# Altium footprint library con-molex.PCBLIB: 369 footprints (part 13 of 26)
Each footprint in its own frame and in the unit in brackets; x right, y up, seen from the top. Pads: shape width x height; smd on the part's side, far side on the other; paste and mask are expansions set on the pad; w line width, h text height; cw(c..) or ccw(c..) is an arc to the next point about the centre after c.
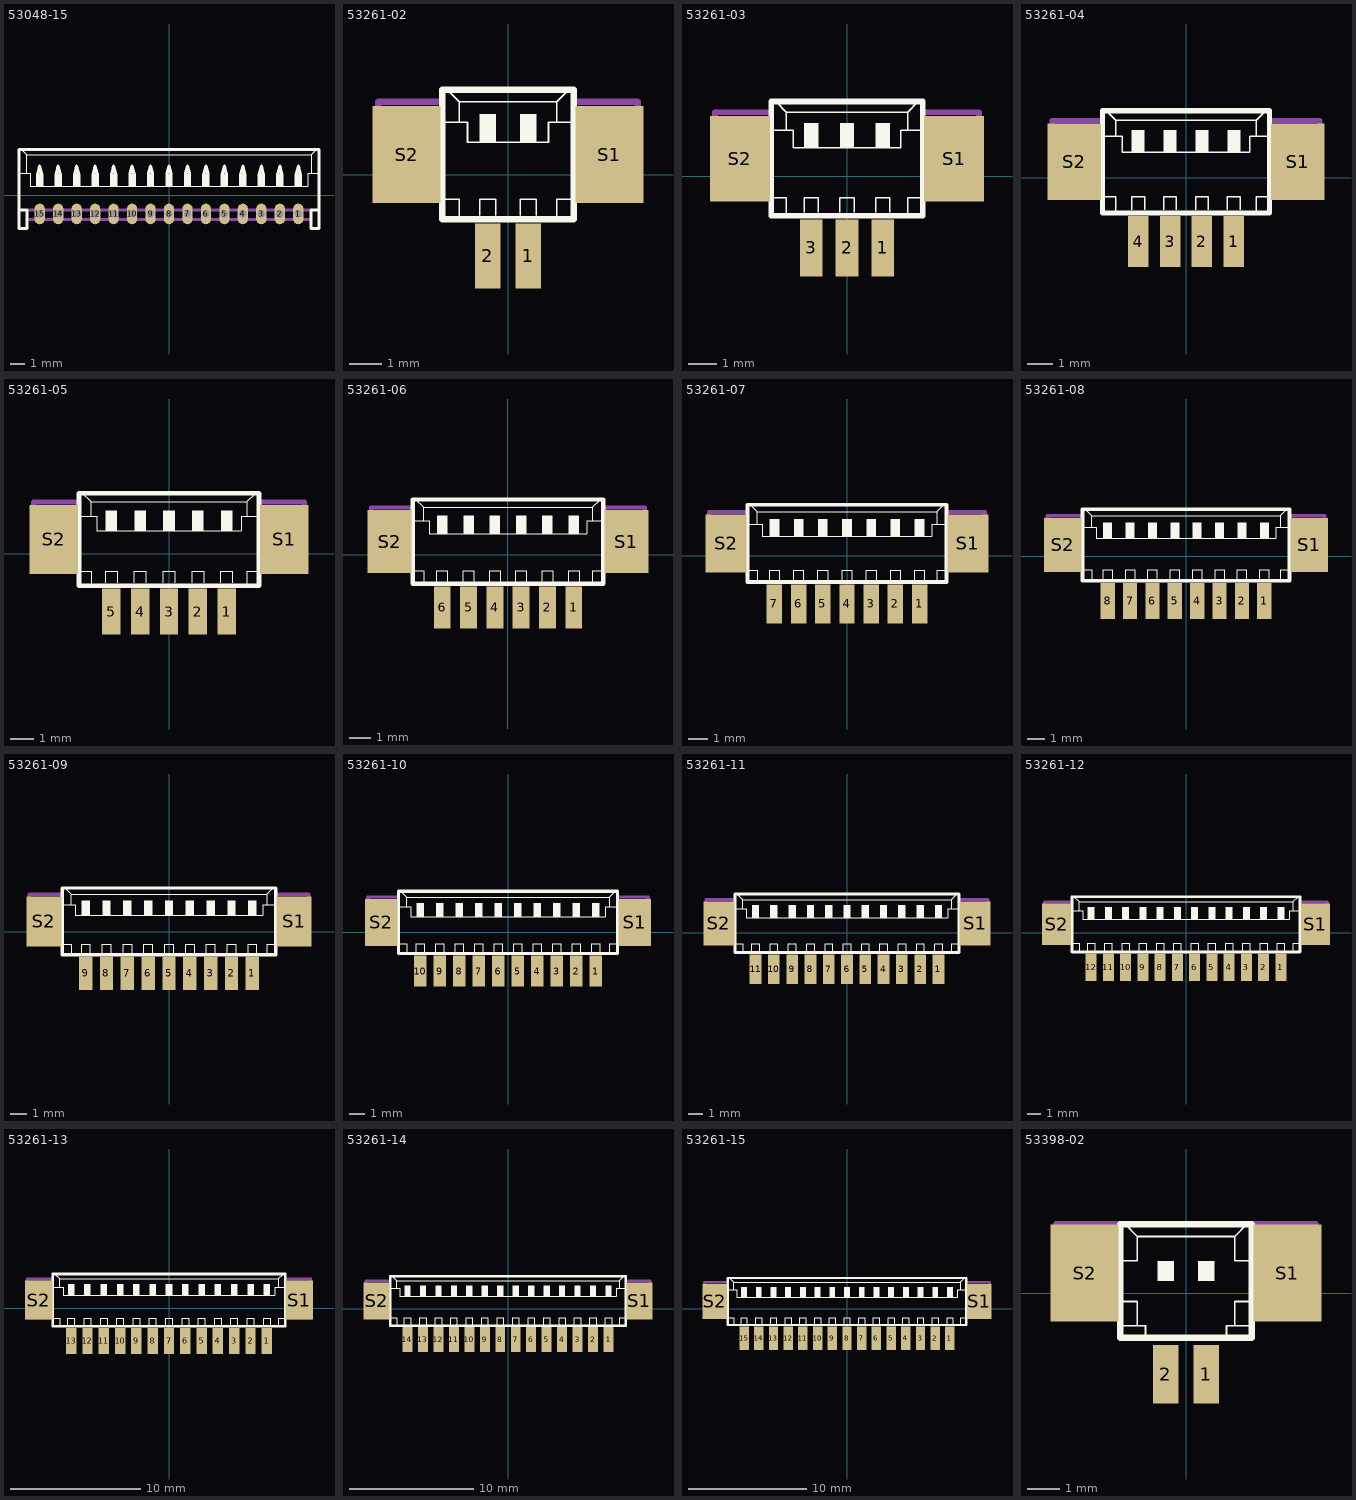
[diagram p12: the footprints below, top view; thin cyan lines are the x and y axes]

## 53048-15 [mil]
pads (15):
  oval 27.5x55 hole 19.69: 1(344.49,-49.21) 2(295.28,-49.21) 3(246.06,-49.21) 4(196.85,-49.21) 5(147.64,-49.21) 6(98.43,-49.21) 7(49.21,-49.21) 8(0,-49.21) 9(-49.21,-49.21) 10(-98.43,-49.21) 11(-147.64,-49.21) 12(-196.85,-49.21) 13(-246.06,-49.21) 14(-295.28,-49.21) 15(-344.49,-49.21)
Top Overlay:
  rectangle: -354.33,24.61 -334.65,59.06
  rectangle: -305.12,24.61 -285.43,59.06
  rectangle: -255.91,24.61 -236.22,59.06
  rectangle: -206.69,24.61 -187.01,59.06
  rectangle: -157.48,24.61 -137.8,59.06
  rectangle: -108.27,24.61 -88.58,59.06
  rectangle: -59.06,24.61 -39.37,59.06
  rectangle: -9.84,24.61 9.84,59.06
  rectangle: 39.37,24.61 59.06,59.06
  rectangle: 88.58,24.61 108.27,59.06
  rectangle: 137.8,24.61 157.48,59.06
  rectangle: 187.01,24.61 206.69,59.06
  rectangle: 236.22,24.61 255.91,59.06
  rectangle: 285.43,24.61 305.12,59.06
  rectangle: 334.65,24.61 354.33,59.06
  lines w2: -398.62,59.06 -378.94,59.06 ; -393.7,123.03 -378.94,108.27 ; 393.7,123.03 378.94,108.27 ; 398.62,59.06 378.94,59.06 ; -378.94,59.06 -369.09,59.06 -369.09,24.61 369.09,24.61 369.09,59.06 378.94,59.06 ; -378.94,59.06 -378.94,108.27 ; -378.94,108.27 378.94,108.27 ; 378.94,59.06 378.94,108.27
  lines w8: -398.62,-39.37 -378.94,-39.37 -378.94,-88.58 -399.61,-88.58 -399.61,123.03 -393.7,123.03 393.7,123.03 399.61,123.03 399.61,-88.58 378.94,-88.58 378.94,-39.37 398.62,-39.37 ; -349.41,59.06 -344.49,78.74 -339.57,59.06 ; -300.2,59.06 -295.28,78.74 -290.35,59.06 ; -250.98,59.06 -246.06,78.74 -241.14,59.06 ; -201.77,59.06 -196.85,78.74 -191.93,59.06 ; -152.56,59.06 -147.64,78.74 -142.72,59.06 ; -103.35,59.06 -98.43,78.74 -93.5,59.06 ; -54.13,59.06 -49.21,78.74 -44.29,59.06 ; -4.92,59.06 0,78.74 4.92,59.06 ; 44.29,59.06 49.21,78.74 54.13,59.06 ; 93.5,59.06 98.43,78.74 103.35,59.06 ; 142.72,59.06 147.64,78.74 152.56,59.06 ; 191.93,59.06 196.85,78.74 201.77,59.06 ; 241.14,59.06 246.06,78.74 250.98,59.06 ; 290.35,59.06 295.28,78.74 300.2,59.06 ; 339.57,59.06 344.49,78.74 349.41,59.06
Mechanical 16:
  rectangle: -354.33,-59.06 -334.65,-39.37
  rectangle: -305.12,-59.06 -285.43,-39.37
  rectangle: -255.91,-59.06 -236.22,-39.37
  rectangle: -206.69,-59.06 -187.01,-39.37
  rectangle: -157.48,-59.06 -137.8,-39.37
  rectangle: -108.27,-59.06 -88.58,-39.37
  rectangle: -59.06,-59.06 -39.37,-39.37
  rectangle: -9.84,-59.06 9.84,-39.37
  rectangle: 39.37,-59.06 59.06,-39.37
  rectangle: 88.58,-59.06 108.27,-39.37
  rectangle: 137.8,-59.06 157.48,-39.37
  rectangle: 187.01,-59.06 206.69,-39.37
  rectangle: 236.22,-59.06 255.91,-39.37
  rectangle: 285.43,-59.06 305.12,-39.37
  rectangle: 334.65,-59.06 354.33,-39.37
  lines w8: -378.94,-63.98 -359.25,-63.98 -354.33,-59.06 ; -378.94,-39.37 378.94,-39.37 ; -334.65,-59.06 -329.72,-63.98 -310.04,-63.98 -305.12,-59.06 ; -285.43,-59.06 -280.51,-63.98 -260.83,-63.98 -255.91,-59.06 ; -236.22,-59.06 -231.3,-63.98 -211.61,-63.98 -206.69,-59.06 ; -187.01,-59.06 -182.09,-63.98 -162.4,-63.98 -157.48,-59.06 ; -137.8,-59.06 -132.87,-63.98 -113.19,-63.98 -108.27,-59.06 ; -88.58,-59.06 -83.66,-63.98 -63.98,-63.98 -59.06,-59.06 ; -39.37,-59.06 -34.45,-63.98 -14.76,-63.98 -9.84,-59.06 ; 9.84,-59.06 14.76,-63.98 34.45,-63.98 39.37,-59.06 ; 59.06,-59.06 63.98,-63.98 83.66,-63.98 88.58,-59.06 ; 108.27,-59.06 113.19,-63.98 132.87,-63.98 137.8,-59.06 ; 157.48,-59.06 162.4,-63.98 182.09,-63.98 187.01,-59.06 ; 206.69,-59.06 211.61,-63.98 231.3,-63.98 236.22,-59.06 ; 255.91,-59.06 260.83,-63.98 280.51,-63.98 285.43,-59.06 ; 305.12,-59.06 310.04,-63.98 329.72,-63.98 334.65,-59.06 ; 354.33,-59.06 359.25,-63.98 378.94,-63.98

## 53261-02 [mm]
pads (4):
  rect 0.8x2 smd: 1(0.625,-2.5) 2(-0.625,-2.5)
  rect 2.1x3 smd: S1(3.125,0.625) S2(-3.125,0.625)
Top Overlay:
  rectangle: -0.875,1 -0.375,1.875
  rectangle: 0.375,1 0.875,1.875
  lines w0.051: -2,-0.75 -1.5,-0.75 -1.5,-1.375 ; -2,1.625 -1.5,1.625 ; -1.875,2.625 -1.5,2.25 ; -0.875,-1.25 -0.875,-0.75 -0.375,-0.75 -0.375,-1.25 ; 0.375,-1.25 0.375,-0.75 0.875,-0.75 0.875,-1.25 ; 1.5,-1.375 1.5,-0.75 2,-0.75 ; 1.875,2.625 1.5,2.25 ; 2,1.625 1.5,1.625 ; -1.5,1.625 -1.25,1.625 -1.25,1 1.25,1 1.25,1.625 1.5,1.625 ; -1.5,1.625 -1.5,2.25 ; -1.5,2.25 1.5,2.25 ; 1.5,1.625 1.5,2.25
  lines w0.203: -2.025,-1.375 -1.5,-1.375 1.5,-1.375 2.025,-1.375 2.025,2.625 1.875,2.625 -1.875,2.625 -2.025,2.625 -2.025,-1.375
Mechanical 16:
  lines w0.203: -2.125,-0.75 -4,-0.75 -4,2.25 -2.125,2.25 ; 2.125,-0.75 4,-0.75 4,2.25 2.125,2.25
  text "1" at 2.5,-0.25 h2.99

## 53261-03 [mm]
pads (5):
  rect 0.8x2 smd: 1(1.25,-2.5) 2(0,-2.5) 3(-1.25,-2.5)
  rect 2.1x3 smd: S1(3.75,0.625) S2(-3.75,0.625)
Top Overlay:
  rectangle: -1.5,1 -1,1.875
  rectangle: -0.25,1 0.25,1.875
  rectangle: 1,1 1.5,1.875
  lines w0.051: -2.625,-0.75 -2.125,-0.75 -2.125,-1.375 ; -2.625,1.625 -2.125,1.625 ; -2.5,2.625 -2.125,2.25 ; -1.5,-1.25 -1.5,-0.75 -1,-0.75 -1,-1.25 ; -0.25,-1.25 -0.25,-0.75 0.25,-0.75 0.25,-1.25 ; 1,-1.25 1,-0.75 1.5,-0.75 1.5,-1.25 ; 2.125,-1.375 2.125,-0.75 2.625,-0.75 ; 2.5,2.625 2.125,2.25 ; 2.625,1.625 2.125,1.625 ; -2.125,1.625 -1.875,1.625 -1.875,1 1.875,1 1.875,1.625 2.125,1.625 ; -2.125,1.625 -2.125,2.25 ; -2.125,2.25 2.125,2.25 ; 2.125,1.625 2.125,2.25
  lines w0.203: -2.65,-1.375 -2.125,-1.375 2.125,-1.375 2.65,-1.375 2.65,2.625 2.5,2.625 -2.5,2.625 -2.65,2.625 -2.65,-1.375
Mechanical 16:
  lines w0.203: -2.75,-0.75 -4.625,-0.75 -4.625,2.25 -2.75,2.25 ; 2.75,-0.75 4.625,-0.75 4.625,2.25 2.75,2.25
  text "1" at 3.125,-0.25 h2.99

## 53261-04 [mm]
pads (6):
  rect 0.8x2 smd: 1(1.875,-2.5) 2(0.625,-2.5) 3(-0.625,-2.5) 4(-1.875,-2.5)
  rect 2.1x3 smd: S1(4.375,0.625) S2(-4.375,0.625)
Top Overlay:
  rectangle: -2.125,1 -1.625,1.875
  rectangle: -0.875,1 -0.375,1.875
  rectangle: 0.375,1 0.875,1.875
  rectangle: 1.625,1 2.125,1.875
  lines w0.051: -3.25,-0.75 -2.75,-0.75 -2.75,-1.375 ; -3.25,1.625 -2.75,1.625 ; -3.125,2.625 -2.75,2.25 ; -2.125,-1.25 -2.125,-0.75 -1.625,-0.75 -1.625,-1.25 ; -0.875,-1.25 -0.875,-0.75 -0.375,-0.75 -0.375,-1.25 ; 0.375,-1.25 0.375,-0.75 0.875,-0.75 0.875,-1.25 ; 1.625,-1.25 1.625,-0.75 2.125,-0.75 2.125,-1.25 ; 2.75,-1.375 2.75,-0.75 3.25,-0.75 ; 3.125,2.625 2.75,2.25 ; 3.25,1.625 2.75,1.625 ; -2.75,1.625 -2.5,1.625 -2.5,1 2.5,1 2.5,1.625 2.75,1.625 ; -2.75,1.625 -2.75,2.25 ; -2.75,2.25 2.75,2.25 ; 2.75,1.625 2.75,2.25
  lines w0.203: -3.275,-1.375 -2.75,-1.375 2.75,-1.375 3.275,-1.375 3.275,2.625 3.125,2.625 -3.125,2.625 -3.275,2.625 -3.275,-1.375
Mechanical 16:
  lines w0.203: -3.375,-0.75 -5.25,-0.75 -5.25,2.25 -3.375,2.25 ; 3.375,-0.75 5.25,-0.75 5.25,2.25 3.375,2.25
  text "1" at 3.75,-0.25 h2.99

## 53261-05 [mm]
pads (7):
  rect 0.8x2 smd: 1(2.5,-2.5) 2(1.25,-2.5) 3(0,-2.5) 4(-1.25,-2.5) 5(-2.5,-2.5)
  rect 2.1x3 smd: S1(5,0.625) S2(-5,0.625)
Top Overlay:
  rectangle: -2.75,1 -2.25,1.875
  rectangle: -1.5,1 -1,1.875
  rectangle: -0.25,1 0.25,1.875
  rectangle: 1,1 1.5,1.875
  rectangle: 2.25,1 2.75,1.875
  lines w0.051: -3.875,-0.75 -3.375,-0.75 -3.375,-1.375 ; -3.875,1.625 -3.375,1.625 ; -3.75,2.625 -3.375,2.25 ; -2.75,-1.25 -2.75,-0.75 -2.25,-0.75 -2.25,-1.25 ; -1.5,-1.25 -1.5,-0.75 -1,-0.75 -1,-1.25 ; -0.25,-1.25 -0.25,-0.75 0.25,-0.75 0.25,-1.25 ; 1,-1.25 1,-0.75 1.5,-0.75 1.5,-1.25 ; 2.25,-1.25 2.25,-0.75 2.75,-0.75 2.75,-1.25 ; 3.375,-1.375 3.375,-0.75 3.875,-0.75 ; 3.75,2.625 3.375,2.25 ; 3.875,1.625 3.375,1.625 ; -3.375,1.625 -3.125,1.625 -3.125,1 3.125,1 3.125,1.625 3.375,1.625 ; -3.375,1.625 -3.375,2.25 ; -3.375,2.25 3.375,2.25 ; 3.375,1.625 3.375,2.25
  lines w0.203: -3.9,-1.375 -3.375,-1.375 3.375,-1.375 3.9,-1.375 3.9,2.625 3.75,2.625 -3.75,2.625 -3.9,2.625 -3.9,-1.375
Mechanical 16:
  lines w0.203: -4,-0.75 -5.875,-0.75 -5.875,2.25 -4,2.25 ; 4,-0.75 5.875,-0.75 5.875,2.25 4,2.25
  text "1" at 4.375,-0.25 h2.99

## 53261-06 [mm]
pads (8):
  rect 0.8x2 smd: 1(3.125,-2.5) 2(1.875,-2.5) 3(0.625,-2.5) 4(-0.625,-2.5) 5(-1.875,-2.5) 6(-3.125,-2.5)
  rect 2.1x3 smd: S1(5.625,0.625) S2(-5.625,0.625)
Top Overlay:
  rectangle: -3.375,1 -2.875,1.875
  rectangle: -2.125,1 -1.625,1.875
  rectangle: -0.875,1 -0.375,1.875
  rectangle: 0.375,1 0.875,1.875
  rectangle: 1.625,1 2.125,1.875
  rectangle: 2.875,1 3.375,1.875
  lines w0.051: -4.5,-0.75 -4,-0.75 -4,-1.375 ; -4.5,1.625 -4,1.625 ; -4.375,2.625 -4,2.25 ; -3.375,-1.25 -3.375,-0.75 -2.875,-0.75 -2.875,-1.25 ; -2.125,-1.25 -2.125,-0.75 -1.625,-0.75 -1.625,-1.25 ; -0.875,-1.25 -0.875,-0.75 -0.375,-0.75 -0.375,-1.25 ; 0.375,-1.25 0.375,-0.75 0.875,-0.75 0.875,-1.25 ; 1.625,-1.25 1.625,-0.75 2.125,-0.75 2.125,-1.25 ; 2.875,-1.25 2.875,-0.75 3.375,-0.75 3.375,-1.25 ; 4,-1.375 4,-0.75 4.5,-0.75 ; 4.375,2.625 4,2.25 ; 4.5,1.625 4,1.625 ; -4,1.625 -3.75,1.625 -3.75,1 3.75,1 3.75,1.625 4,1.625 ; -4,1.625 -4,2.25 ; -4,2.25 4,2.25 ; 4,1.625 4,2.25
  lines w0.203: -4.525,-1.375 -4,-1.375 4,-1.375 4.525,-1.375 4.525,2.625 4.375,2.625 -4.375,2.625 -4.525,2.625 -4.525,-1.375
Mechanical 16:
  lines w0.203: -4.625,-0.75 -6.5,-0.75 -6.5,2.25 -4.625,2.25 ; 4.625,-0.75 6.5,-0.75 6.5,2.25 4.625,2.25
  text "1" at 5,-0.25 h2.99

## 53261-07 [mm]
pads (9):
  rect 0.8x2 smd: 1(3.75,-2.5) 2(2.5,-2.5) 3(1.25,-2.5) 4(0,-2.5) 5(-1.25,-2.5) 6(-2.5,-2.5) 7(-3.75,-2.5)
  rect 2.1x3 smd: S1(6.25,0.625) S2(-6.25,0.625)
Top Overlay:
  rectangle: -4,1 -3.5,1.875
  rectangle: -2.75,1 -2.25,1.875
  rectangle: -1.5,1 -1,1.875
  rectangle: -0.25,1 0.25,1.875
  rectangle: 1,1 1.5,1.875
  rectangle: 2.25,1 2.75,1.875
  rectangle: 3.5,1 4,1.875
  lines w0.051: -5.125,-0.75 -4.625,-0.75 -4.625,-1.375 ; -5.125,1.625 -4.625,1.625 ; -5,2.625 -4.625,2.25 ; -4,-1.25 -4,-0.75 -3.5,-0.75 -3.5,-1.25 ; -2.75,-1.25 -2.75,-0.75 -2.25,-0.75 -2.25,-1.25 ; -1.5,-1.25 -1.5,-0.75 -1,-0.75 -1,-1.25 ; -0.25,-1.25 -0.25,-0.75 0.25,-0.75 0.25,-1.25 ; 1,-1.25 1,-0.75 1.5,-0.75 1.5,-1.25 ; 2.25,-1.25 2.25,-0.75 2.75,-0.75 2.75,-1.25 ; 3.5,-1.25 3.5,-0.75 4,-0.75 4,-1.25 ; 4.625,-1.375 4.625,-0.75 5.125,-0.75 ; 5,2.625 4.625,2.25 ; 5.125,1.625 4.625,1.625 ; -4.625,1.625 -4.375,1.625 -4.375,1 4.375,1 4.375,1.625 4.625,1.625 ; -4.625,1.625 -4.625,2.25 ; -4.625,2.25 4.625,2.25 ; 4.625,1.625 4.625,2.25
  lines w0.203: -5.15,-1.375 -4.625,-1.375 4.625,-1.375 5.15,-1.375 5.15,2.625 5,2.625 -5,2.625 -5.15,2.625 -5.15,-1.375
Mechanical 16:
  lines w0.203: -5.25,-0.75 -7.125,-0.75 -7.125,2.25 -5.25,2.25 ; 5.25,-0.75 7.125,-0.75 7.125,2.25 5.25,2.25
  text "1" at 5.75,-0.25 h2.99

## 53261-08 [mm]
pads (10):
  rect 0.8x2 smd: 1(4.375,-2.5) 2(3.125,-2.5) 3(1.875,-2.5) 4(0.625,-2.5) 5(-0.625,-2.5) 6(-1.875,-2.5) 7(-3.125,-2.5) 8(-4.375,-2.5)
  rect 2.1x3 smd: S1(6.875,0.625) S2(-6.875,0.625)
Top Overlay:
  rectangle: -4.625,1 -4.125,1.875
  rectangle: -3.375,1 -2.875,1.875
  rectangle: -2.125,1 -1.625,1.875
  rectangle: -0.875,1 -0.375,1.875
  rectangle: 0.375,1 0.875,1.875
  rectangle: 1.625,1 2.125,1.875
  rectangle: 2.875,1 3.375,1.875
  rectangle: 4.125,1 4.625,1.875
  lines w0.051: -5.75,-0.75 -5.25,-0.75 -5.25,-1.375 ; -5.75,1.625 -5.25,1.625 ; -5.625,2.625 -5.25,2.25 ; -4.625,-1.25 -4.625,-0.75 -4.125,-0.75 -4.125,-1.25 ; -3.375,-1.25 -3.375,-0.75 -2.875,-0.75 -2.875,-1.25 ; -2.125,-1.25 -2.125,-0.75 -1.625,-0.75 -1.625,-1.25 ; -0.875,-1.25 -0.875,-0.75 -0.375,-0.75 -0.375,-1.25 ; 0.375,-1.25 0.375,-0.75 0.875,-0.75 0.875,-1.25 ; 1.625,-1.25 1.625,-0.75 2.125,-0.75 2.125,-1.25 ; 2.875,-1.25 2.875,-0.75 3.375,-0.75 3.375,-1.25 ; 4.125,-1.25 4.125,-0.75 4.625,-0.75 4.625,-1.25 ; 5.25,-1.375 5.25,-0.75 5.75,-0.75 ; 5.625,2.625 5.25,2.25 ; 5.75,1.625 5.25,1.625 ; -5.25,1.625 -5,1.625 -5,1 5,1 5,1.625 5.25,1.625 ; -5.25,1.625 -5.25,2.25 ; -5.25,2.25 5.25,2.25 ; 5.25,1.625 5.25,2.25
  lines w0.203: -5.775,-1.375 -5.25,-1.375 5.25,-1.375 5.775,-1.375 5.775,2.625 5.625,2.625 -5.625,2.625 -5.775,2.625 -5.775,-1.375
Mechanical 16:
  lines w0.203: -5.875,-0.75 -7.75,-0.75 -7.75,2.25 -5.875,2.25 ; 5.875,-0.75 7.75,-0.75 7.75,2.25 5.875,2.25
  text "1" at 6.25,-0.25 h2.99

## 53261-09 [mm]
pads (11):
  rect 0.8x2 smd: 1(5,-2.5) 2(3.75,-2.5) 3(2.5,-2.5) 4(1.25,-2.5) 5(0,-2.5) 6(-1.25,-2.5) 7(-2.5,-2.5) 8(-3.75,-2.5) 9(-5,-2.5)
  rect 2.1x3 smd: S1(7.5,0.625) S2(-7.5,0.625)
Top Overlay:
  rectangle: -5.25,1 -4.75,1.875
  rectangle: -4,1 -3.5,1.875
  rectangle: -2.75,1 -2.25,1.875
  rectangle: -1.5,1 -1,1.875
  rectangle: -0.25,1 0.25,1.875
  rectangle: 1,1 1.5,1.875
  rectangle: 2.25,1 2.75,1.875
  rectangle: 3.5,1 4,1.875
  rectangle: 4.75,1 5.25,1.875
  lines w0.051: -6.375,-0.75 -5.875,-0.75 -5.875,-1.375 ; -6.375,1.625 -5.875,1.625 ; -6.25,2.625 -5.875,2.25 ; -5.25,-1.25 -5.25,-0.75 -4.75,-0.75 -4.75,-1.25 ; -4,-1.25 -4,-0.75 -3.5,-0.75 -3.5,-1.25 ; -2.75,-1.25 -2.75,-0.75 -2.25,-0.75 -2.25,-1.25 ; -1.5,-1.25 -1.5,-0.75 -1,-0.75 -1,-1.25 ; -0.25,-1.25 -0.25,-0.75 0.25,-0.75 0.25,-1.25 ; 1,-1.25 1,-0.75 1.5,-0.75 1.5,-1.25 ; 2.25,-1.25 2.25,-0.75 2.75,-0.75 2.75,-1.25 ; 3.5,-1.25 3.5,-0.75 4,-0.75 4,-1.25 ; 4.75,-1.25 4.75,-0.75 5.25,-0.75 5.25,-1.25 ; 5.875,-1.375 5.875,-0.75 6.375,-0.75 ; 6.25,2.625 5.875,2.25 ; 6.375,1.625 5.875,1.625 ; -5.875,1.625 -5.625,1.625 -5.625,1 5.625,1 5.625,1.625 5.875,1.625 ; -5.875,1.625 -5.875,2.25 ; -5.875,2.25 5.875,2.25 ; 5.875,1.625 5.875,2.25
  lines w0.203: -6.4,-1.375 -5.875,-1.375 5.875,-1.375 6.4,-1.375 6.4,2.625 6.25,2.625 -6.25,2.625 -6.4,2.625 -6.4,-1.375
Mechanical 16:
  lines w0.203: -6.5,-0.75 -8.375,-0.75 -8.375,2.25 -6.5,2.25 ; 6.5,-0.75 8.375,-0.75 8.375,2.25 6.5,2.25
  text "1" at 6.875,-0.25 h2.99

## 53261-10 [mm]
pads (12):
  rect 0.8x2 smd: 1(5.625,-2.5) 2(4.375,-2.5) 3(3.125,-2.5) 4(1.875,-2.5) 5(0.625,-2.5) 6(-0.625,-2.5) 7(-1.875,-2.5) 8(-3.125,-2.5) 9(-4.375,-2.5) 10(-5.625,-2.5)
  rect 2.1x3 smd: S1(8.125,0.625) S2(-8.125,0.625)
Top Overlay:
  rectangle: -5.875,1 -5.375,1.875
  rectangle: -4.625,1 -4.125,1.875
  rectangle: -3.375,1 -2.875,1.875
  rectangle: -2.125,1 -1.625,1.875
  rectangle: -0.875,1 -0.375,1.875
  rectangle: 0.375,1 0.875,1.875
  rectangle: 1.625,1 2.125,1.875
  rectangle: 2.875,1 3.375,1.875
  rectangle: 4.125,1 4.625,1.875
  rectangle: 5.375,1 5.875,1.875
  lines w0.051: -7,-0.75 -6.5,-0.75 -6.5,-1.375 ; -7,1.625 -6.5,1.625 ; -6.875,2.625 -6.5,2.25 ; -5.875,-1.25 -5.875,-0.75 -5.375,-0.75 -5.375,-1.25 ; -4.625,-1.25 -4.625,-0.75 -4.125,-0.75 -4.125,-1.25 ; -3.375,-1.25 -3.375,-0.75 -2.875,-0.75 -2.875,-1.25 ; -2.125,-1.25 -2.125,-0.75 -1.625,-0.75 -1.625,-1.25 ; -0.875,-1.25 -0.875,-0.75 -0.375,-0.75 -0.375,-1.25 ; 0.375,-1.25 0.375,-0.75 0.875,-0.75 0.875,-1.25 ; 1.625,-1.25 1.625,-0.75 2.125,-0.75 2.125,-1.25 ; 2.875,-1.25 2.875,-0.75 3.375,-0.75 3.375,-1.25 ; 4.125,-1.25 4.125,-0.75 4.625,-0.75 4.625,-1.25 ; 5.375,-1.25 5.375,-0.75 5.875,-0.75 5.875,-1.25 ; 6.5,-1.375 6.5,-0.75 7,-0.75 ; 6.875,2.625 6.5,2.25 ; 7,1.625 6.5,1.625 ; -6.5,1.625 -6.25,1.625 -6.25,1 6.25,1 6.25,1.625 6.5,1.625 ; -6.5,1.625 -6.5,2.25 ; -6.5,2.25 6.5,2.25 ; 6.5,1.625 6.5,2.25
  lines w0.203: -7.025,-1.375 -6.5,-1.375 6.5,-1.375 7.025,-1.375 7.025,2.625 6.875,2.625 -6.875,2.625 -7.025,2.625 -7.025,-1.375
Mechanical 16:
  lines w0.203: -7.125,-0.75 -9,-0.75 -9,2.25 -7.125,2.25 ; 7.125,-0.75 9,-0.75 9,2.25 7.125,2.25
  text "1" at 7.5,-0.25 h2.99

## 53261-11 [mm]
pads (13):
  rect 0.8x2 smd: 1(6.25,-2.5) 2(5,-2.5) 3(3.75,-2.5) 4(2.5,-2.5) 5(1.25,-2.5) 6(0,-2.5) 7(-1.25,-2.5) 8(-2.5,-2.5) 9(-3.75,-2.5) 10(-5,-2.5) 11(-6.25,-2.5)
  rect 2.1x3 smd: S1(8.75,0.625) S2(-8.75,0.625)
Top Overlay:
  rectangle: -6.5,1 -6,1.875
  rectangle: -5.25,1 -4.75,1.875
  rectangle: -4,1 -3.5,1.875
  rectangle: -2.75,1 -2.25,1.875
  rectangle: -1.5,1 -1,1.875
  rectangle: -0.25,1 0.25,1.875
  rectangle: 1,1 1.5,1.875
  rectangle: 2.25,1 2.75,1.875
  rectangle: 3.5,1 4,1.875
  rectangle: 4.75,1 5.25,1.875
  rectangle: 6,1 6.5,1.875
  lines w0.051: -7.625,-0.75 -7.125,-0.75 -7.125,-1.375 ; -7.625,1.625 -7.125,1.625 ; -7.5,2.625 -7.125,2.25 ; -6.5,-1.25 -6.5,-0.75 -6,-0.75 -6,-1.25 ; -5.25,-1.25 -5.25,-0.75 -4.75,-0.75 -4.75,-1.25 ; -4,-1.25 -4,-0.75 -3.5,-0.75 -3.5,-1.25 ; -2.75,-1.25 -2.75,-0.75 -2.25,-0.75 -2.25,-1.25 ; -1.5,-1.25 -1.5,-0.75 -1,-0.75 -1,-1.25 ; -0.25,-1.25 -0.25,-0.75 0.25,-0.75 0.25,-1.25 ; 1,-1.25 1,-0.75 1.5,-0.75 1.5,-1.25 ; 2.25,-1.25 2.25,-0.75 2.75,-0.75 2.75,-1.25 ; 3.5,-1.25 3.5,-0.75 4,-0.75 4,-1.25 ; 4.75,-1.25 4.75,-0.75 5.25,-0.75 5.25,-1.25 ; 6,-1.25 6,-0.75 6.5,-0.75 6.5,-1.25 ; 7.125,-1.375 7.125,-0.75 7.625,-0.75 ; 7.5,2.625 7.125,2.25 ; 7.625,1.625 7.125,1.625 ; -7.125,1.625 -6.875,1.625 -6.875,1 6.875,1 6.875,1.625 7.125,1.625 ; -7.125,1.625 -7.125,2.25 ; -7.125,2.25 7.125,2.25 ; 7.125,1.625 7.125,2.25
  lines w0.203: -7.65,-1.375 -7.125,-1.375 7.125,-1.375 7.65,-1.375 7.65,2.625 7.5,2.625 -7.5,2.625 -7.65,2.625 -7.65,-1.375
Mechanical 16:
  lines w0.203: -7.75,-0.75 -9.625,-0.75 -9.625,2.25 -7.75,2.25 ; 7.75,-0.75 9.625,-0.75 9.625,2.25 7.75,2.25
  text "1" at 8.25,-0.25 h2.99

## 53261-12 [mm]
pads (14):
  rect 0.8x2 smd: 1(6.875,-2.5) 2(5.625,-2.5) 3(4.375,-2.5) 4(3.125,-2.5) 5(1.875,-2.5) 6(0.625,-2.5) 7(-0.625,-2.5) 8(-1.875,-2.5) 9(-3.125,-2.5) 10(-4.375,-2.5) 11(-5.625,-2.5) 12(-6.875,-2.5)
  rect 2.1x3 smd: S1(9.375,0.625) S2(-9.375,0.625)
Top Overlay:
  rectangle: -7.125,1 -6.625,1.875
  rectangle: -5.875,1 -5.375,1.875
  rectangle: -4.625,1 -4.125,1.875
  rectangle: -3.375,1 -2.875,1.875
  rectangle: -2.125,1 -1.625,1.875
  rectangle: -0.875,1 -0.375,1.875
  rectangle: 0.375,1 0.875,1.875
  rectangle: 1.625,1 2.125,1.875
  rectangle: 2.875,1 3.375,1.875
  rectangle: 4.125,1 4.625,1.875
  rectangle: 5.375,1 5.875,1.875
  rectangle: 6.625,1 7.125,1.875
  lines w0.051: -8.25,-0.75 -7.75,-0.75 -7.75,-1.375 ; -8.25,1.625 -7.75,1.625 ; -8.125,2.625 -7.75,2.25 ; -7.125,-1.25 -7.125,-0.75 -6.625,-0.75 -6.625,-1.25 ; -5.875,-1.25 -5.875,-0.75 -5.375,-0.75 -5.375,-1.25 ; -4.625,-1.25 -4.625,-0.75 -4.125,-0.75 -4.125,-1.25 ; -3.375,-1.25 -3.375,-0.75 -2.875,-0.75 -2.875,-1.25 ; -2.125,-1.25 -2.125,-0.75 -1.625,-0.75 -1.625,-1.25 ; -0.875,-1.25 -0.875,-0.75 -0.375,-0.75 -0.375,-1.25 ; 0.375,-1.25 0.375,-0.75 0.875,-0.75 0.875,-1.25 ; 1.625,-1.25 1.625,-0.75 2.125,-0.75 2.125,-1.25 ; 2.875,-1.25 2.875,-0.75 3.375,-0.75 3.375,-1.25 ; 4.125,-1.25 4.125,-0.75 4.625,-0.75 4.625,-1.25 ; 5.375,-1.25 5.375,-0.75 5.875,-0.75 5.875,-1.25 ; 6.625,-1.25 6.625,-0.75 7.125,-0.75 7.125,-1.25 ; 7.75,-1.375 7.75,-0.75 8.25,-0.75 ; 8.125,2.625 7.75,2.25 ; 8.25,1.625 7.75,1.625 ; -7.75,1.625 -7.5,1.625 -7.5,1 7.5,1 7.5,1.625 7.75,1.625 ; -7.75,1.625 -7.75,2.25 ; -7.75,2.25 7.75,2.25 ; 7.75,1.625 7.75,2.25
  lines w0.203: -8.275,-1.375 -7.75,-1.375 7.75,-1.375 8.275,-1.375 8.275,2.625 8.125,2.625 -8.125,2.625 -8.275,2.625 -8.275,-1.375
Mechanical 16:
  lines w0.203: -8.375,-0.75 -10.25,-0.75 -10.25,2.25 -8.375,2.25 ; 8.375,-0.75 10.25,-0.75 10.25,2.25 8.375,2.25
  text "1" at 8.75,-0.25 h2.99

## 53261-13 [mm]
pads (15):
  rect 0.8x2 smd: 1(7.5,-2.5) 2(6.25,-2.5) 3(5,-2.5) 4(3.75,-2.5) 5(2.5,-2.5) 6(1.25,-2.5) 7(0,-2.5) 8(-1.25,-2.5) 9(-2.5,-2.5) 10(-3.75,-2.5) 11(-5,-2.5) 12(-6.25,-2.5) 13(-7.5,-2.5)
  rect 2.1x3 smd: S1(10,0.625) S2(-10,0.625)
Top Overlay:
  rectangle: -7.75,1 -7.25,1.875
  rectangle: -6.5,1 -6,1.875
  rectangle: -5.25,1 -4.75,1.875
  rectangle: -4,1 -3.5,1.875
  rectangle: -2.75,1 -2.25,1.875
  rectangle: -1.5,1 -1,1.875
  rectangle: -0.25,1 0.25,1.875
  rectangle: 1,1 1.5,1.875
  rectangle: 2.25,1 2.75,1.875
  rectangle: 3.5,1 4,1.875
  rectangle: 4.75,1 5.25,1.875
  rectangle: 6,1 6.5,1.875
  rectangle: 7.25,1 7.75,1.875
  lines w0.051: -8.875,-0.75 -8.375,-0.75 -8.375,-1.375 ; -8.875,1.625 -8.375,1.625 ; -8.75,2.625 -8.375,2.25 ; -7.75,-1.25 -7.75,-0.75 -7.25,-0.75 -7.25,-1.25 ; -6.5,-1.25 -6.5,-0.75 -6,-0.75 -6,-1.25 ; -5.25,-1.25 -5.25,-0.75 -4.75,-0.75 -4.75,-1.25 ; -4,-1.25 -4,-0.75 -3.5,-0.75 -3.5,-1.25 ; -2.75,-1.25 -2.75,-0.75 -2.25,-0.75 -2.25,-1.25 ; -1.5,-1.25 -1.5,-0.75 -1,-0.75 -1,-1.25 ; -0.25,-1.25 -0.25,-0.75 0.25,-0.75 0.25,-1.25 ; 1,-1.25 1,-0.75 1.5,-0.75 1.5,-1.25 ; 2.25,-1.25 2.25,-0.75 2.75,-0.75 2.75,-1.25 ; 3.5,-1.25 3.5,-0.75 4,-0.75 4,-1.25 ; 4.75,-1.25 4.75,-0.75 5.25,-0.75 5.25,-1.25 ; 6,-1.25 6,-0.75 6.5,-0.75 6.5,-1.25 ; 7.25,-1.25 7.25,-0.75 7.75,-0.75 7.75,-1.25 ; 8.375,-1.375 8.375,-0.75 8.875,-0.75 ; 8.75,2.625 8.375,2.25 ; 8.875,1.625 8.375,1.625 ; -8.375,1.625 -8.125,1.625 -8.125,1 8.125,1 8.125,1.625 8.375,1.625 ; -8.375,1.625 -8.375,2.25 ; -8.375,2.25 8.375,2.25 ; 8.375,1.625 8.375,2.25
  lines w0.203: -8.9,-1.375 -8.375,-1.375 8.375,-1.375 8.9,-1.375 8.9,2.625 8.75,2.625 -8.75,2.625 -8.9,2.625 -8.9,-1.375
Mechanical 16:
  lines w0.203: -9,-0.75 -10.875,-0.75 -10.875,2.25 -9,2.25 ; 9,-0.75 10.875,-0.75 10.875,2.25 9,2.25
  text "1" at 9.5,-0.25 h2.99

## 53261-14 [mm]
pads (16):
  rect 0.8x2 smd: 1(8.125,-2.5) 2(6.875,-2.5) 3(5.625,-2.5) 4(4.375,-2.5) 5(3.125,-2.5) 6(1.875,-2.5) 7(0.625,-2.5) 8(-0.625,-2.5) 9(-1.875,-2.5) 10(-3.125,-2.5) 11(-4.375,-2.5) 12(-5.625,-2.5) 13(-6.875,-2.5) 14(-8.125,-2.5)
  rect 2.1x3 smd: S1(10.625,0.625) S2(-10.625,0.625)
Top Overlay:
  rectangle: -8.375,1 -7.875,1.875
  rectangle: -7.125,1 -6.625,1.875
  rectangle: -5.875,1 -5.375,1.875
  rectangle: -4.625,1 -4.125,1.875
  rectangle: -3.375,1 -2.875,1.875
  rectangle: -2.125,1 -1.625,1.875
  rectangle: -0.875,1 -0.375,1.875
  rectangle: 0.375,1 0.875,1.875
  rectangle: 1.625,1 2.125,1.875
  rectangle: 2.875,1 3.375,1.875
  rectangle: 4.125,1 4.625,1.875
  rectangle: 5.375,1 5.875,1.875
  rectangle: 6.625,1 7.125,1.875
  rectangle: 7.875,1 8.375,1.875
  lines w0.051: -9.5,-0.75 -9,-0.75 -9,-1.375 ; -9.5,1.625 -9,1.625 ; -9.375,2.625 -9,2.25 ; -8.375,-1.25 -8.375,-0.75 -7.875,-0.75 -7.875,-1.25 ; -7.125,-1.25 -7.125,-0.75 -6.625,-0.75 -6.625,-1.25 ; -5.875,-1.25 -5.875,-0.75 -5.375,-0.75 -5.375,-1.25 ; -4.625,-1.25 -4.625,-0.75 -4.125,-0.75 -4.125,-1.25 ; -3.375,-1.25 -3.375,-0.75 -2.875,-0.75 -2.875,-1.25 ; -2.125,-1.25 -2.125,-0.75 -1.625,-0.75 -1.625,-1.25 ; -0.875,-1.25 -0.875,-0.75 -0.375,-0.75 -0.375,-1.25 ; 0.375,-1.25 0.375,-0.75 0.875,-0.75 0.875,-1.25 ; 1.625,-1.25 1.625,-0.75 2.125,-0.75 2.125,-1.25 ; 2.875,-1.25 2.875,-0.75 3.375,-0.75 3.375,-1.25 ; 4.125,-1.25 4.125,-0.75 4.625,-0.75 4.625,-1.25 ; 5.375,-1.25 5.375,-0.75 5.875,-0.75 5.875,-1.25 ; 6.625,-1.25 6.625,-0.75 7.125,-0.75 7.125,-1.25 ; 7.875,-1.25 7.875,-0.75 8.375,-0.75 8.375,-1.25 ; 9,-1.375 9,-0.75 9.5,-0.75 ; 9.375,2.625 9,2.25 ; 9.5,1.625 9,1.625 ; -9,1.625 -8.75,1.625 -8.75,1 8.75,1 8.75,1.625 9,1.625 ; -9,1.625 -9,2.25 ; -9,2.25 9,2.25 ; 9,1.625 9,2.25
  lines w0.203: -9.525,-1.375 -9,-1.375 9,-1.375 9.525,-1.375 9.525,2.625 9.375,2.625 -9.375,2.625 -9.525,2.625 -9.525,-1.375
Mechanical 16:
  lines w0.203: -9.625,-0.75 -11.5,-0.75 -11.5,2.25 -9.625,2.25 ; 9.625,-0.75 11.5,-0.75 11.5,2.25 9.625,2.25
  text "1" at 10,-0.25 h2.99

## 53261-15 [mm]
pads (17):
  rect 0.8x2 smd: 1(8.75,-2.5) 2(7.5,-2.5) 3(6.25,-2.5) 4(5,-2.5) 5(3.75,-2.5) 6(2.5,-2.5) 7(1.25,-2.5) 8(0,-2.5) 9(-1.25,-2.5) 10(-2.5,-2.5) 11(-3.75,-2.5) 12(-5,-2.5) 13(-6.25,-2.5) 14(-7.5,-2.5) 15(-8.75,-2.5)
  rect 2.1x3 smd: S1(11.25,0.625) S2(-11.25,0.625)
Top Overlay:
  rectangle: -9,1 -8.5,1.875
  rectangle: -7.75,1 -7.25,1.875
  rectangle: -6.5,1 -6,1.875
  rectangle: -5.25,1 -4.75,1.875
  rectangle: -4,1 -3.5,1.875
  rectangle: -2.75,1 -2.25,1.875
  rectangle: -1.5,1 -1,1.875
  rectangle: -0.25,1 0.25,1.875
  rectangle: 1,1 1.5,1.875
  rectangle: 2.25,1 2.75,1.875
  rectangle: 3.5,1 4,1.875
  rectangle: 4.75,1 5.25,1.875
  rectangle: 6,1 6.5,1.875
  rectangle: 7.25,1 7.75,1.875
  rectangle: 8.5,1 9,1.875
  lines w0.051: -10.125,-0.75 -9.625,-0.75 -9.625,-1.375 ; -10.125,1.625 -9.625,1.625 ; -10,2.625 -9.625,2.25 ; -9,-1.25 -9,-0.75 -8.5,-0.75 -8.5,-1.25 ; -7.75,-1.25 -7.75,-0.75 -7.25,-0.75 -7.25,-1.25 ; -6.5,-1.25 -6.5,-0.75 -6,-0.75 -6,-1.25 ; -5.25,-1.25 -5.25,-0.75 -4.75,-0.75 -4.75,-1.25 ; -4,-1.25 -4,-0.75 -3.5,-0.75 -3.5,-1.25 ; -2.75,-1.25 -2.75,-0.75 -2.25,-0.75 -2.25,-1.25 ; -1.5,-1.25 -1.5,-0.75 -1,-0.75 -1,-1.25 ; -0.25,-1.25 -0.25,-0.75 0.25,-0.75 0.25,-1.25 ; 1,-1.25 1,-0.75 1.5,-0.75 1.5,-1.25 ; 2.25,-1.25 2.25,-0.75 2.75,-0.75 2.75,-1.25 ; 3.5,-1.25 3.5,-0.75 4,-0.75 4,-1.25 ; 4.75,-1.25 4.75,-0.75 5.25,-0.75 5.25,-1.25 ; 6,-1.25 6,-0.75 6.5,-0.75 6.5,-1.25 ; 7.25,-1.25 7.25,-0.75 7.75,-0.75 7.75,-1.25 ; 8.5,-1.25 8.5,-0.75 9,-0.75 9,-1.25 ; 9.625,-1.375 9.625,-0.75 10.125,-0.75 ; 10,2.625 9.625,2.25 ; 10.125,1.625 9.625,1.625 ; -9.625,1.625 -9.375,1.625 -9.375,1 9.375,1 9.375,1.625 9.625,1.625 ; -9.625,1.625 -9.625,2.25 ; -9.625,2.25 9.625,2.25 ; 9.625,1.625 9.625,2.25
  lines w0.203: -10.15,-1.375 -9.625,-1.375 9.625,-1.375 10.15,-1.375 10.15,2.625 10,2.625 -10,2.625 -10.15,2.625 -10.15,-1.375
Mechanical 16:
  lines w0.203: -10.25,-0.75 -12.125,-0.75 -12.125,2.25 -10.25,2.25 ; 10.25,-0.75 12.125,-0.75 12.125,2.25 10.25,2.25
  text "1" at 10.75,-0.25 h2.99

## 53398-02 [mm]
pads (4):
  rect 0.8x1.8 smd: 1(0.625,-2.5) 2(-0.625,-2.5)
  rect 2.1x3 smd: S1(3.125,0.625) S2(-3.125,0.625)
Top Overlay:
  rectangle: -0.875,0.375 -0.375,1
  rectangle: 0.375,0.375 0.875,1
  lines w0.051: -2,-1 -1.5,-1 ; -2,-0.25 -1.5,-0.25 -1.5,-1 ; -2,1 -1.5,1 -1.5,1.75 ; -1.875,2.125 -1.5,1.75 ; -1.25,-1.375 -1.25,-1 -1.5,-1 ; 1.25,-1.375 1.25,-1 1.5,-1 ; 1.875,2.125 1.5,1.75 ; 2,-1 1.5,-1 ; 2,-0.25 1.5,-0.25 1.5,-1 ; 2,1 1.5,1 1.5,1.75 ; -1.5,1.75 1.5,1.75
  lines w0.203: -2.025,-1.375 -1.25,-1.375 1.25,-1.375 2.025,-1.375 2.025,2.125 1.875,2.125 -1.875,2.125 -2.025,2.125 -2.025,-1.375
Mechanical 16:
  lines w0.203: -2.125,-0.75 -4,-0.75 -4,2.125 -2.125,2.125 ; 2.125,-0.75 4,-0.75 4,2.125 2.125,2.125
  text "1" at 2.5,-0.25 h2.99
